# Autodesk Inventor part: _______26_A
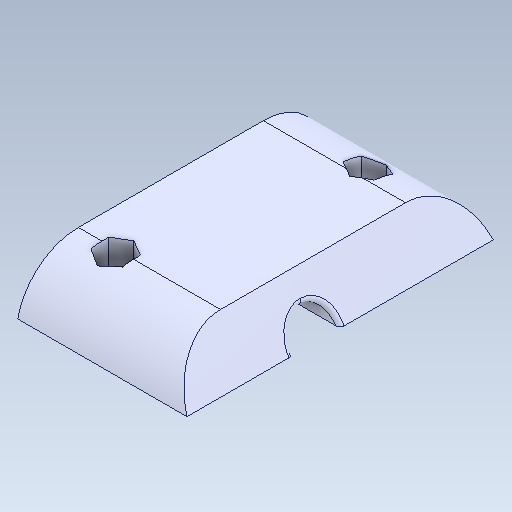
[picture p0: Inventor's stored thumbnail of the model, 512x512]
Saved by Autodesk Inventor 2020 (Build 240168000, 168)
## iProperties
Created: 2017-09
Part Number: _______26_A
Material: Générique
Document SubType Name: Modeling
Designer: bruno
Density: 1 g/cm^3
Appearance: Par défaut
Author: bruno
Sending System: SolidWorks 2016
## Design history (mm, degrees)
feature "Importée1"
node "Solide1"
